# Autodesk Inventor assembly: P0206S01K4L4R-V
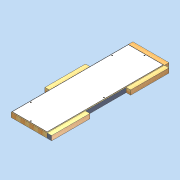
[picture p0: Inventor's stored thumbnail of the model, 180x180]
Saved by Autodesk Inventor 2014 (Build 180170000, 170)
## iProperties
Justset: False
Created: 2011-04
Part Number: P0206S01K4L4R-V
Document SubType Name: Assembly
Designer: david.appleford
Description: 0.5w x 1.5w 01 Panel - 5 Locks 4 Lugs RH
Mass: 22000 g
Surface Area: 29419.9 cm^2
Volume: 86479.4 cm^3
Density: 0.254396 g/cm^3
Cost Center: £93.00
Author: david.appleford
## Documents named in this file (5)
- C:\Documents and Settings\john.everitt\Local Settings\My Documents\Vault\Production MkII\VIRTUAL ELEMENTS\Virtual Walls\Virtual Timber + MgO\P0206S01K5L4R-V.iam
- C:\Documents and Settings\john.everitt\Local Settings\My Documents\Vault\Production MkII\Virtual Elements\LA02M3.ipt
- C:\Documents and Settings\john.everitt\Local Settings\My Documents\Vault\Production MkII\Virtual Elements\LA02E3.ipt
- C:\Documents and Settings\john.everitt\Local Settings\My Documents\Vault\Production MkII\VIRTUAL ELEMENTS\Virtual Lugs\Superceded Lugs\LA02C3V.ipt
- C:\Documents and Settings\john.everitt\Local Settings\My Documents\Vault\Production MkII\VIRTUAL ELEMENTS\Virtual Walls\Virtual Timber + MgO\P0206S01K5-V.ipt
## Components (5 placed, 4 different names)
1. P0206S01K5-V:1 — Flush:3, Flush:4, Mate:5, Flush:10, Mate:6, Flush:11, Mate:7, Mate:8, Flush:12, Flush:13, Mate:9
2. LA02E3:1 — Flush:3, Flush:4, Mate:9
3. LA02M3:2 — Mate:5, Flush:10
4. LA02C3V:1 — Mate:6, Flush:11, Mate:7
5. LA02C3V:2 — Mate:8, Flush:12, Flush:13
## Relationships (11: Flush 6, Mate 5)
- Flush:3: P0206S01K5-V:1 ↔ LA02E3:1
- Flush:4: P0206S01K5-V:1 ↔ LA02E3:1
- Mate:5: P0206S01K5-V:1 ↔ LA02M3:2
- Flush:10: P0206S01K5-V:1 ↔ LA02M3:2
- Mate:6: P0206S01K5-V:1 ↔ LA02C3V:1
- Flush:11: P0206S01K5-V:1 ↔ LA02C3V:1
- Mate:7: P0206S01K5-V:1 ↔ LA02C3V:1
- Mate:8: P0206S01K5-V:1 ↔ LA02C3V:2
- Flush:12: P0206S01K5-V:1 ↔ LA02C3V:2
- Flush:13: P0206S01K5-V:1 ↔ LA02C3V:2
- Mate:9: P0206S01K5-V:1 ↔ LA02E3:1
## Named parameters: t = 1 mm, Cl = 2 mm
